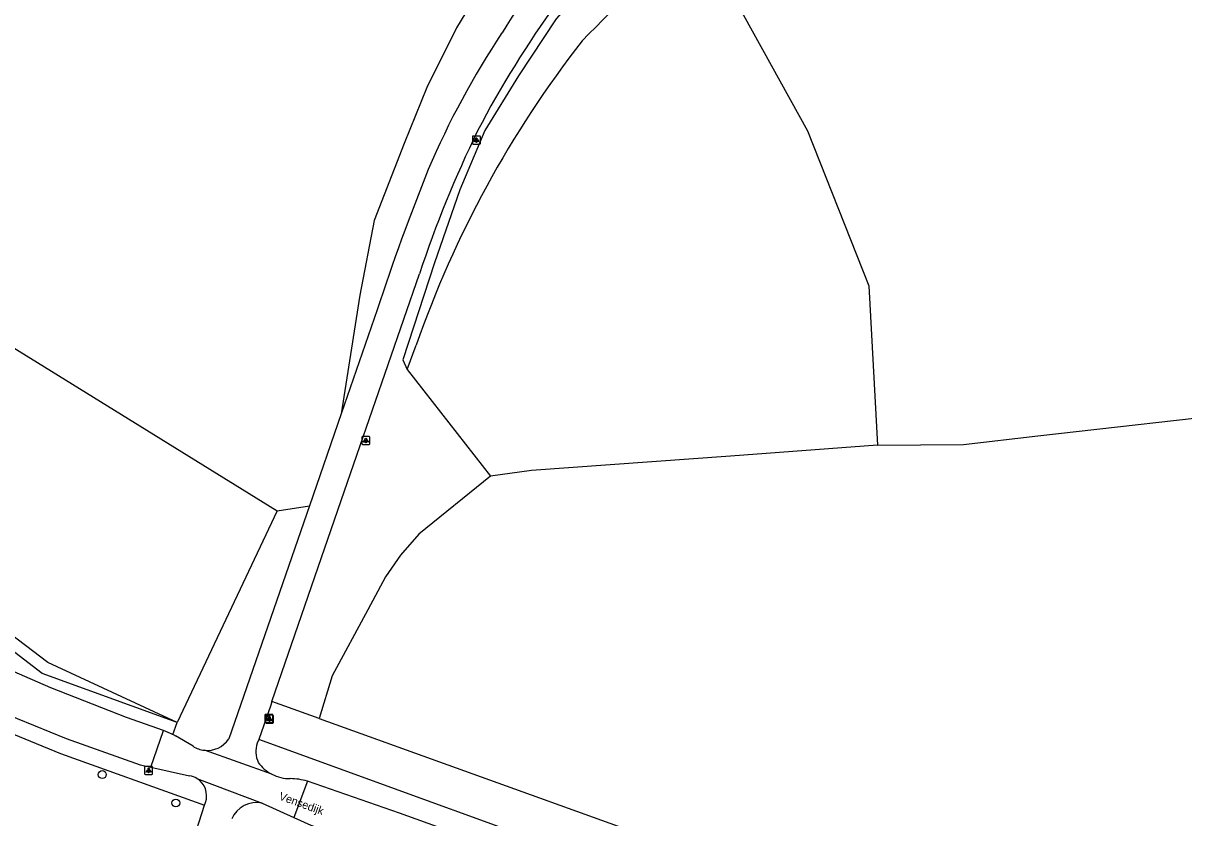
# Model space of a CAD drawing. Extents: x 156061 to 157804, y 383451 to 385640.
# Drawn here: x 156290.3 to 156435.3, y 385168.8 to 385268.1 of the extents above; entities that cross this region are included whole.
import ezdxf

# ---------------------------------------------------------------- set-up
doc = ezdxf.new("R2010")
doc.units = 0
for name, color, linetype in [('IMGEO_Boom', 7, 'Continuous'), ('IMGEO_Fietspad_gesloten', 7, 'Continuous'), ('IMGEO_Grasland_overig', 7, 'Continuous'), ('IMGEO_Groenvoorziening', 7, 'Continuous'), ('IMGEO_Lichtpunt', 7, 'Continuous'), ('IMGEO_Loofbos', 7, 'Continuous'), ('IMGEO_Openbare_ruimte_label', 7, 'Continuous'), ('IMGEO_Rijbaan_lokaal_gesloten', 7, 'Continuous'), ('IMGEO_Rijbaan_lokaal_open', 7, 'Continuous')]:
    doc.layers.add(name, color=color, linetype=linetype)

msp = doc.modelspace()

# ---------------------------------------------------------------- linework, layer by layer
at = {"layer": 'IMGEO_Boom'}
for centre in [(156300.17, 385174.2), (156309.36, 385170.65)]:
    msp.add_circle(centre, 0.489, dxfattribs=at)
at = {"layer": 'IMGEO_Fietspad_gesloten'}
for points in [[(156321.37, 385183.34), (156330.03, 385208.44), (156339.79, 385236.75)], [(156334.5, 385232.27), (156330, 385219.26)], [(156330, 385219.26), (156326.04, 385207.79)], [(156326.04, 385207.79), (156315.97, 385178.65)], [(156321.37, 385183.34), (156321.21, 385182.86), (156319.71, 385178.59)], [(156319.71, 385178.59), (156319.54, 385178.11)], [(156309.7, 385160.2), (156312.96, 385170.38)], [(156312.96, 385170.38), (156313.07, 385170.71)]]:
    msp.add_lwpolyline(points, dxfattribs=at)
for centre, radius, start, end in [((156419.84, 385224.19), 81.74, 135.5078, 148.5517), ((156460.54, 385195.33), 128.04, 144.0442, 152.4088), ((156439.35, 385207.6), 107.12, 146.4268, 156.7981), ((156483.26, 385188.84), 151.26, 154.2181, 161.533), ((156640.31, 385130.63), 322.26, 158.2968, 161.6158), ((156313.27, 385180.46), 3.25, 264.0584, 326.0209), ((156322.67, 385177.07), 3.3, 161.6624, 203.9687), ((156323.65, 385178.64), 4.95, 216.0636, 242.364), ((156310.66, 385171.55), 2.55, 340.8035, 58.4029), ((156319.45, 385167.33), 3.38, 77.8821, 157.0215)]:
    msp.add_arc(centre, radius, start, end, dxfattribs=at)
at = {"layer": 'IMGEO_Grasland_overig'}
for points in [[(156281.34, 385182.66), (156286.73, 385180.21), (156294.95, 385176.85), (156311.92, 385170.76), (156312.96, 385170.38)], [(156513.09, 385108.31), (156319.71, 385178.59)]]:
    msp.add_lwpolyline(points, dxfattribs=at)
at = {"layer": 'IMGEO_Groenvoorziening'}
for points in [[(156309.52, 385180.69), (156292.68, 385186.81), (156275.14, 385200.29), (156253.97, 385221.66), (156247.68, 385227.99), (156228.5, 385250), (156140.32, 385351.17)], [(156367.92, 385281.22), (156364.01, 385276.73), (156356.89, 385268.59), (156352.17, 385261.5), (156347.97, 385254.67), (156344.82, 385247.24), (156341.68, 385238.14), (156337.71, 385226), (156338.27, 385224.81)], [(156397.01, 385215.36), (156407.76, 385215.44), (156417.02, 385216.5), (156444.32, 385219.59), (156487.42, 385224.63), (156500, 385226.03), (156522.58, 385228.54), (156556.36, 385232.36), (156590.31, 385235.94)], [(156348.65, 385211.46), (156339.71, 385204.22), (156337.43, 385201.61), (156335.55, 385198.92), (156333.35, 385194.76), (156328.87, 385186.53), (156327.27, 385181.21)], [(156327.27, 385181.21), (156321.37, 385183.34)], [(156308.97, 385179.21), (156309.52, 385180.69)], [(156327.27, 385181.21), (156500, 385119), (156514.99, 385113.6)]]:
    msp.add_lwpolyline(points, dxfattribs=at)
at = {"layer": 'IMGEO_Lichtpunt'}
for p, q in [((156346.4, 385253.86), (156346.4, 385253.05)), ((156346.4, 385253.86), (156346.4, 385253.05)), ((156347.31, 385253.95), (156346.5, 385253.95)), ((156347.31, 385253.95), (156346.5, 385253.95)), ((156346.5, 385252.95), (156347.31, 385252.95)), ((156346.5, 385252.95), (156347.31, 385252.95)), ((156347.4, 385253.05), (156347.4, 385253.86)), ((156347.4, 385253.05), (156347.4, 385253.86)), ((156332.6, 385216.33), (156332.6, 385215.53)), ((156332.6, 385216.33), (156332.6, 385215.53)), ((156333.5, 385216.43), (156332.69, 385216.43)), ((156333.5, 385216.43), (156332.69, 385216.43)), ((156332.69, 385215.43), (156333.5, 385215.43)), ((156332.69, 385215.43), (156333.5, 385215.43)), ((156333.59, 385215.53), (156333.59, 385216.33)), ((156333.59, 385215.53), (156333.59, 385216.33)), ((156320.49, 385181.62), (156320.49, 385180.81)), ((156320.49, 385181.62), (156320.49, 385180.81)), ((156320.56, 385181.53), (156320.56, 385180.72)), ((156320.56, 385181.53), (156320.56, 385180.72)), ((156321.4, 385181.71), (156320.59, 385181.71)), ((156321.4, 385181.71), (156320.59, 385181.71)), ((156320.59, 385180.72), (156321.4, 385180.72)), ((156320.59, 385180.72), (156321.4, 385180.72)), ((156321.47, 385181.63), (156320.66, 385181.63)), ((156321.47, 385181.63), (156320.66, 385181.63)), ((156320.66, 385180.63), (156321.47, 385180.63)), ((156320.66, 385180.63), (156321.47, 385180.63)), ((156321.49, 385180.81), (156321.49, 385181.62)), ((156321.49, 385180.81), (156321.49, 385181.62)), ((156321.56, 385180.72), (156321.56, 385181.53)), ((156321.56, 385180.72), (156321.56, 385181.53)), ((156305.46, 385175.12), (156305.46, 385174.31)), ((156305.46, 385175.12), (156305.46, 385174.31)), ((156306.37, 385175.21), (156305.56, 385175.21)), ((156306.37, 385175.21), (156305.56, 385175.21)), ((156306.46, 385174.31), (156306.46, 385175.12)), ((156306.46, 385174.31), (156306.46, 385175.12)), ((156305.56, 385174.21), (156306.37, 385174.21)), ((156305.56, 385174.21), (156306.37, 385174.21))]:
    msp.add_line(p, q, dxfattribs=at)
for points in [[(156346.78, 385253.52), (156346.82, 385253.49), (156346.63, 385253.23), (156346.59, 385253.26), (156346.78, 385253.52)], [(156346.88, 385253.47), (156346.93, 385253.47), (156346.93, 385253.15), (156346.88, 385253.15), (156346.88, 385253.47)], [(156346.99, 385253.49), (156347.03, 385253.52), (156347.21, 385253.26), (156347.18, 385253.23), (156346.99, 385253.49)], [(156332.97, 385216), (156333.01, 385215.97), (156332.82, 385215.71), (156332.78, 385215.73), (156332.97, 385216)], [(156333.07, 385215.95), (156333.12, 385215.95), (156333.12, 385215.63), (156333.07, 385215.63), (156333.07, 385215.95)], [(156333.18, 385215.97), (156333.22, 385216), (156333.41, 385215.73), (156333.37, 385215.71), (156333.18, 385215.97)], [(156320.87, 385181.28), (156320.91, 385181.25), (156320.72, 385180.99), (156320.68, 385181.02), (156320.87, 385181.28)], [(156320.94, 385181.19), (156320.98, 385181.17), (156320.79, 385180.9), (156320.75, 385180.93), (156320.94, 385181.19)], [(156320.97, 385181.23), (156321.02, 385181.23), (156321.02, 385180.91), (156320.97, 385180.91), (156320.97, 385181.23)], [(156321.04, 385181.15), (156321.09, 385181.15), (156321.09, 385180.82), (156321.04, 385180.82), (156321.04, 385181.15)], [(156321.08, 385181.25), (156321.12, 385181.28), (156321.31, 385181.02), (156321.27, 385180.99), (156321.08, 385181.25)], [(156321.15, 385181.17), (156321.19, 385181.19), (156321.37, 385180.93), (156321.34, 385180.9), (156321.15, 385181.17)], [(156305.84, 385174.78), (156305.88, 385174.75), (156305.69, 385174.49), (156305.65, 385174.52), (156305.84, 385174.78)], [(156305.94, 385174.73), (156305.99, 385174.73), (156305.99, 385174.41), (156305.94, 385174.41), (156305.94, 385174.73)], [(156306.05, 385174.75), (156306.09, 385174.78), (156306.27, 385174.52), (156306.24, 385174.49), (156306.05, 385174.75)]]:
    msp.add_lwpolyline(points, dxfattribs=at)
for centre in [(156346.9, 385253.65), (156333.1, 385216.13), (156320.99, 385181.42), (156321.06, 385181.33), (156305.96, 385174.91)]:
    msp.add_circle(centre, 0.0994, dxfattribs=at)
for centre, start, end in [((156346.5, 385253.86), 90, 180), ((156346.5, 385253.86), 90, 180), ((156346.5, 385253.05), 180, 270), ((156346.5, 385253.05), 180, 270), ((156347.31, 385253.86), 0, 90), ((156347.31, 385253.86), 0, 90), ((156347.31, 385253.05), 270, 0), ((156347.31, 385253.05), 270, 360), ((156332.69, 385216.33), 90, 180), ((156332.69, 385216.33), 90, 180), ((156332.69, 385215.53), 180, 270), ((156332.69, 385215.53), 180, 270), ((156333.5, 385216.33), 0, 90), ((156333.5, 385216.33), 0, 90), ((156333.5, 385215.53), 270, 0), ((156333.5, 385215.53), 270, 360), ((156320.59, 385181.62), 90, 180), ((156320.59, 385181.62), 90, 180), ((156320.59, 385180.81), 180, 270), ((156320.59, 385180.81), 180, 270), ((156320.66, 385181.53), 90, 180), ((156320.66, 385181.53), 90, 180), ((156320.66, 385180.72), 180, 270), ((156320.66, 385180.72), 180, 270), ((156321.4, 385181.62), 0, 90), ((156321.4, 385181.62), 0, 90), ((156321.4, 385180.81), 270, 0), ((156321.4, 385180.81), 270, 360), ((156321.47, 385181.53), 0, 90), ((156321.47, 385181.53), 0, 90), ((156321.47, 385180.72), 270, 0), ((156321.47, 385180.72), 270, 360), ((156305.56, 385175.12), 90, 180), ((156305.56, 385175.12), 90, 180), ((156306.37, 385175.12), 0, 90), ((156306.37, 385175.12), 0, 90), ((156305.56, 385174.31), 180, 270), ((156305.56, 385174.31), 180, 270), ((156306.37, 385174.31), 270, 0), ((156306.37, 385174.31), 270, 360)]:
    msp.add_arc(centre, 0.0946, start, end, dxfattribs=at)
at = {"layer": 'IMGEO_Loofbos'}
for points in [[(156194.26, 385390.62), (156200.47, 385373.29), (156207.27, 385318.03), (156209.43, 385312.37), (156244.77, 385266.89), (156273.47, 385237.16), (156322.02, 385207.14)], [(156309.52, 385180.69), (156293.37, 385188.19), (156275.56, 385201.73), (156250.07, 385230.68), (156233.31, 385250), (156141.33, 385355.97)], [(156363.07, 385294.56), (156356, 385285.37), (156350.11, 385276.89), (156344.4, 385267.46), (156340.71, 385260.04), (156337.88, 385253.04), (156334.14, 385243.42), (156332.33, 385234.09), (156330, 385219.26)], [(156373.92, 385279.43), (156376.83, 385275.37), (156388.25, 385254.61), (156395.94, 385235.25), (156397.01, 385215.36)], [(156338.27, 385224.81), (156339.39, 385227.83)], [(156338.27, 385224.81), (156348.65, 385211.46)], [(156397.01, 385215.36), (156378.64, 385213.99), (156353.79, 385212.19), (156348.65, 385211.46)], [(156322.02, 385207.14), (156309.52, 385180.69)], [(156322.02, 385207.14), (156326.04, 385207.79)]]:
    msp.add_lwpolyline(points, dxfattribs=at)
for centre, radius, start, end in [((156666.69, 384968.07), 427.38, 133.2377, 135.833), ((156464.68, 385184.19), 132.67, 142.0093, 160.7962)]:
    msp.add_arc(centre, radius, start, end, dxfattribs=at)
at = {"layer": 'IMGEO_Rijbaan_lokaal_gesloten'}
for points in [[(156201.88, 385240.23), (156213.17, 385230.57), (156225.41, 385219.91), (156231.26, 385215.26), (156236.64, 385211.45), (156239.32, 385209.47), (156244.86, 385205.55), (156254.93, 385198.99), (156262.87, 385194.29), (156267.92, 385191.49), (156277.89, 385186.42), (156282.17, 385184.48), (156287.52, 385182.05), (156295.67, 385178.72), (156304.92, 385175.4), (156306.23, 385175.11)], [(156307.83, 385179.7), (156303.19, 385181.33), (156293.74, 385185.04), (156286.53, 385188.15), (156279.91, 385191.24), (156273.87, 385194.24), (156265.52, 385198.71), (156259.71, 385202.04), (156253.3, 385205.96), (156243.64, 385212.33), (156238.37, 385216.19), (156237.64, 385216.75)], [(156306.23, 385175.11), (156307.83, 385179.7)], [(156325.8, 385173.38), (156324.12, 385168.82)], [(156556.61, 385090.38), (156500, 385110.73), (156337.29, 385169.36), (156325.8, 385173.38)], [(156324.12, 385168.82), (156326.22, 385167.86), (156431.78, 385130.12), (156500, 385105.74), (156557.53, 385085.07), (156567.97, 385081.12), (156578.06, 385077.45), (156590.93, 385073.63)]]:
    msp.add_lwpolyline(points, dxfattribs=at)
at = {"layer": 'IMGEO_Rijbaan_lokaal_open'}
for points in [[(156311.51, 385177.74), (156309.32, 385179.02)], [(156321.36, 385174.26), (156312.94, 385177.23)], [(156306.23, 385175.11), (156311.09, 385174.06)], [(156312, 385173.72), (156320.16, 385170.64)], [(156320.16, 385170.64), (156324.12, 385168.82)]]:
    msp.add_lwpolyline(points, dxfattribs=at)
for centre, radius, start, end in [((156304.42, 385170.29), 10.01, 62.993, 70.0873), ((156305.42, 385172.13), 7.91, 60.5129, 63.3762), ((156313.27, 385180.45), 3.23, 236.9547, 264.0983), ((156310.67, 385171.57), 2.52, 58.2895, 80.3763), ((156323.65, 385178.62), 4.93, 242.3247, 270.1076), ((156323.57, 385165.59), 8.1, 74.0115, 89.3996)]:
    msp.add_arc(centre, radius, start, end, dxfattribs=at)

# ---------------------------------------------------------------- texts
at = {"layer": 'IMGEO_Openbare_ruimte_label'}
msp.add_text('Vensedijk', height=1, rotation=340.1882, dxfattribs=at).set_placement((156322.17, 385171.1))

doc.saveas('drawing.dxf')
